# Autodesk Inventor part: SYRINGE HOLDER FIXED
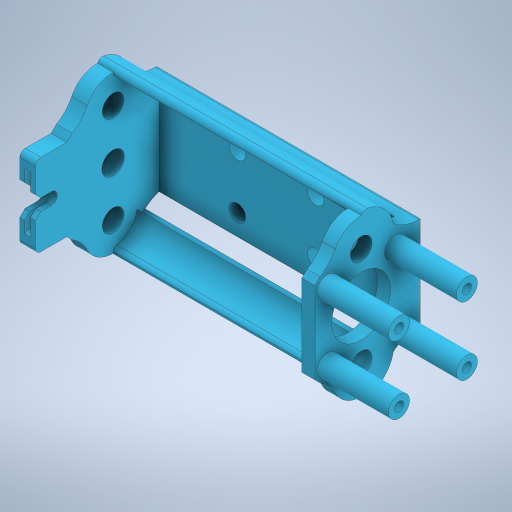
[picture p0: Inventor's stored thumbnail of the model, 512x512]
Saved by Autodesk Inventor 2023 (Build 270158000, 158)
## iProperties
Created: 2025-07
Part Number: SYRINGE HOLDER FIXED
Material: Generic
Document SubType Name: Modeling
Designer: erjon
Density: 1 g/cm^3
Appearance: Default
Author: erjon
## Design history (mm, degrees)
feature "Base1"
body "Solid1"
